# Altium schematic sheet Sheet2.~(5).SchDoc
size B; SheetNumber: 1; SheetTotal: 1
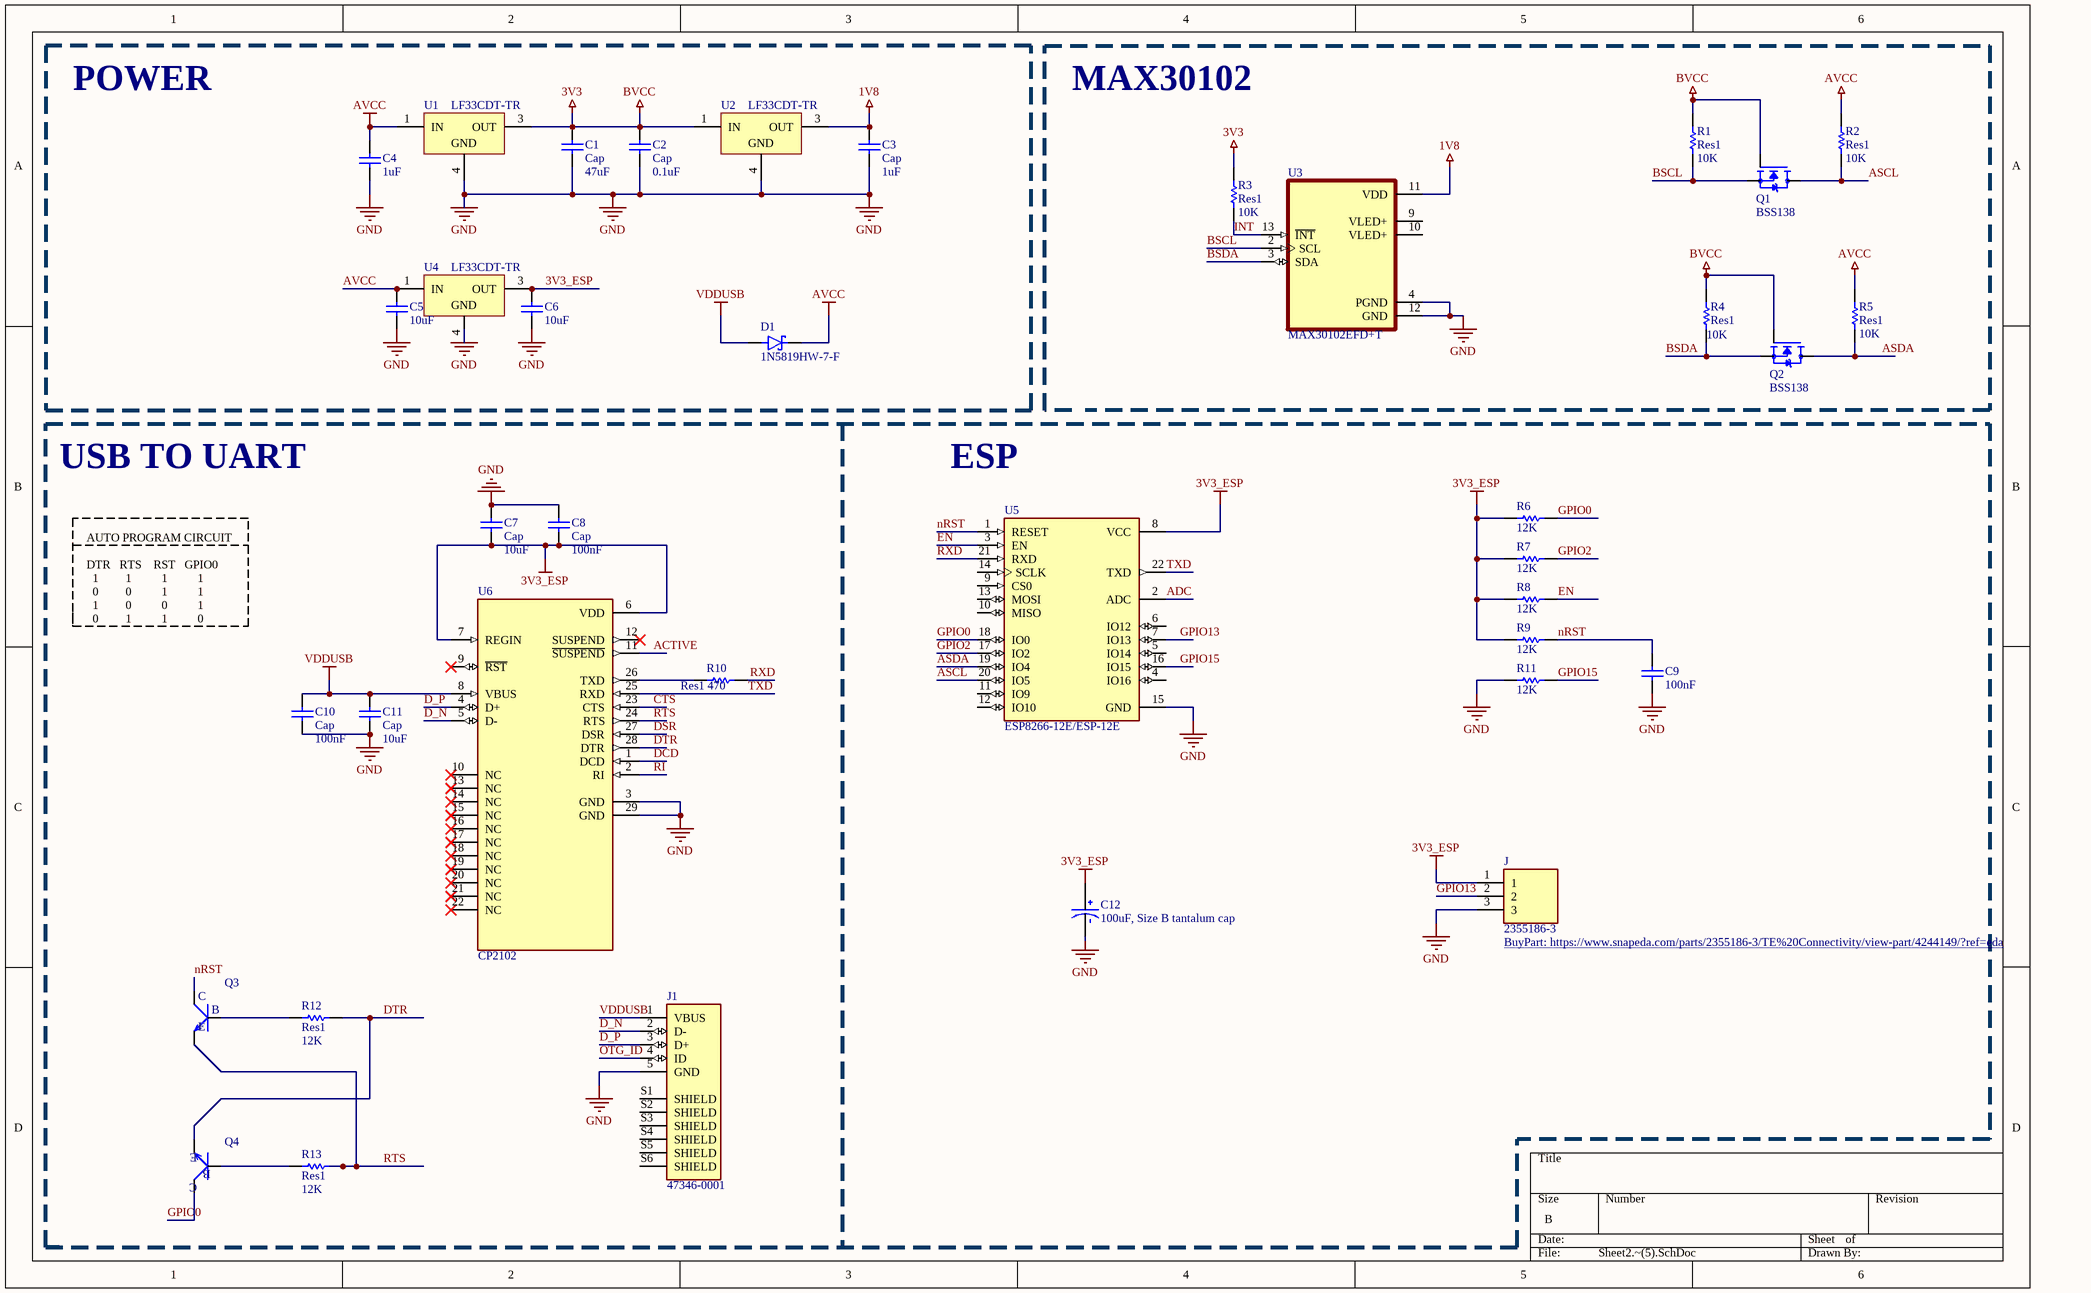
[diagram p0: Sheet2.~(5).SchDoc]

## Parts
C1  Cap  value 47uF  [RAD-0.3]
C2  Cap  value 0.1uF  [RAD-0.3]
C3  Cap  value 1uF  [RAD-0.3]
C4  1uF  [CAP805]
C5  10uF  [CAP805]
C6  10uF  [CAP805]
C7  Cap  value 10uF  [RAD-0.3]
C8  Cap  value 100nF  [RAD-0.3]
C9  100nF  [CAP805]
C10  Cap  value 100nF  [RAD-0.3]
C11  Cap  value 10uF  [RAD-0.3]
C12  100uF, Size B tantalum cap  [CAPMC6032X260]
D1  1N5819HW-7-F  [SOD3715X145N]
J  2355186-3  [TE_2355186-3]
J1  47346-0001  [MOLEX_47346-0001]
Q1  BSS138  [SOT95P240X111-3N]
Q2  BSS138  [SOT95P240X111-3N]
Q3  SMD-TRANSISTORS-NPN-25V-500MW(SOT-23)  [SOT-23]  (value not drawn)
Q4  SMD-TRANSISTORS-NPN-25V-500MW(SOT-23)  [SOT-23]  (value not drawn)
R1  Res1  value 10K  [AXIAL-0.3]
R2  Res1  value 10K  [AXIAL-0.3]
R3  Res1  value 10K  [AXIAL-0.3]
R4  Res1  value 10K  [AXIAL-0.3]
R5  Res1  value 10K  [AXIAL-0.3]
R6  12K  [RES0805]
R7  12K  [RES0805]
R8  12K  [RES0805]
R9  12K  [RES0805]
R10  Res1  value 470  [AXIAL-0.3]
R11  12K  [RES0805]
R12  Res1  value 12K  [AXIAL-0.3]
R13  Res1  value 12K  [AXIAL-0.3]
U1  LF33CDT-TR  [TO-252_N]
U2  LF33CDT-TR  [TO-252_N]
U3  MAX30102EFD+T  [XDCR_MAX30101EFD+]
U4  LF33CDT-TR  [TO-252_N]
U5  ESP8266-12E/ESP-12E  [XCVR_ESP8266-12E/ESP-12E]
U6  CP2102  [QFN50P500X500X100-29N]

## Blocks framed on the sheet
POWER: C1-C6 D1 U1 U2 U4

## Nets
1V8: C3.2 U2.3(OUT) U3.11(VDD)
3V3: C1.2 C2.2 Q1.1(G) Q2.1(G) R1.2 R3.2 R4.2 U1.3(OUT) U2.1(IN)  [also labelled BVCC]
3V3_ESP: C6.2 C7.2 C8.2 C12.POS J.1 R6.1 R7.1 R8.1 R9.1 U4.3(OUT) U5.8(VCC) U6.6(VDD) U6.7(REGIN)
AVCC: C4.2 C5.2 D1.C(K) R2.2 R5.2 U1.1(IN) U4.1(IN)
GND: C1.1 C2.1 C3.1 C4.1 C5.1 C6.1 C7.1 C8.1 C9.1 C10.1 C11.1 C12.NEG J.3 J1.5(GND) R11.1 U1.4(GND) U2.4(GND) U3.4(PGND) U3.12(GND) U4.4(GND) U5.15(GND) U6.3(GND) U6.29(GND)
VDDUSB: C10.2 C11.2 D1.A J1.1(VBUS) U6.8(VBUS)
ACTIVE: U6.11(~{SUSPEND})
ADC: U5.2(ADC)
ASCL: Q1.3(D) R2.1 U5.20(IO5)
ASDA: Q2.3(D) R5.1 U5.19(IO4)
BSCL: Q1.2(S) R1.1 U3.2(SCL)
BSDA: Q2.2(S) R4.1 U3.3(SDA)
CTS: U6.23(CTS)
D_N: J1.2(D-) U6.5(D-)
D_P: J1.3(D+) U6.4(D+)
DCD: U6.1(DCD)
DSR: U6.27(DSR)
DTR: Q4.2(E) R12.2 U6.28(DTR)
EN: R8.2 U5.3(EN)
GPIO0: Q4.3(C) R6.2 U5.18(IO0)
GPIO2: R7.2 U5.17(IO2)
GPIO13: J.2 U5.7(IO13)
GPIO15: R11.2 U5.16(IO15)
INT: R3.1 U3.13(~{INT})
nRST: C9.2 Q3.3(C) R9.2 U5.1(RESET)
OTG_ID: J1.4(ID)
RI: U6.2(RI)
RTS: Q3.2(E) R13.2 U6.24(RTS)
RXD: R10.2 U5.21(RXD)
TXD: U5.22(TXD) U6.25(RXD)
NetQ3_1: Q3.1(B) R12.1
NetQ4_1: Q4.1(B) R13.1
NetR10_1: R10.1 U6.26(TXD)

Not connected (* = marked no-connect by the designer): J1 S1(SHIELD) S2(SHIELD) S3(SHIELD) S4(SHIELD) S5(SHIELD) S6(SHIELD); U3 9(VLED+) 10(VLED+); U5 4(IO16) 5(IO14) 6(IO12) 9(CS0) 10(MISO) 11(IO9) 12(IO10) 13(MOSI) 14(SCLK); U6 9(~{RST})* 10(NC)* 12(SUSPEND)* 13(NC)* 14(NC)* 15(NC)* 16(NC)* 17(NC)* 18(NC)* 19(NC)* 20(NC)* 21(NC)* 22(NC)*

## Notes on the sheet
- MAX30102
- USB TO UART
- ESP
- AUTO PROGRAM CIRCUIT
  DTR   RTS    RST   GPIO0
  1         1          1          1
  0         0          1          1
  1         0          0          1
  0         1          1          0

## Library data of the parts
C1-C3 C7 C8 C10 C11 = Cap: Capacitor
C4 = CAP SMD PACKAGE: TOTAL CAPACITOR SMD PACK; Designer: Abbas Basereh; Desc.: CAP SMD TOTAL PACKAGES; VALUE: 100nF
C5 C6 C9 = CAP SMD PACKAGE: TOTAL CAPACITOR SMD PACK; Designer: Abbas Basereh; Desc.: CAP SMD TOTAL PACKAGES
C12 = TAJC107K016RNJ: 100µF Molded Tantalum Capacitors 16V 2312 _6032 Metric_ 1Ohm; MF: AVX Interconnect / Elco
D1 = 1N5819HW-7-F: Diode Schottky 40 V 1A Surface Mount SOD-123; MF: Diodes Inc.
J = 2355186-3: Pin 3P,2MM,BRK HDR,SRVT,2.8,0.76AU,BOX 3 POS; MF: TE Connectivity
J1 = 47346-0001: USB - micro B USB 2.0 Receptacle Connector 5 Position Surface Mount, Right Angle; MF: Molex
Q1 Q2 = BSS138: N-Channel 50 V 220mA (Ta) 350mW (Ta) Surface Mount SOT-23-3; MF: onsemi
Q3 Q4 = SMD-TRANSISTORS-NPN-25V-500MW(SOT-23): Bipolar (BJT) Transistor NPN 25 V 500 mA 150MHz 300 mW Surface Mount SOT-23; MF: UMW; MP: S8050
R1-R5 R10 R12 R13 = Res1: Resistor
R6-R9 R11 = RES SMD PACKAGE: TOTAL SMD RESISTOR PACK; Designer: Abbas Basereh; Desc.: RES SMD PAKAGES
U1 U2 U4 = LF33CDT-TR: 500mA, Very Low Drop (0.45V) Voltage Regulator, 3.3V, 3-Pin DPAK, Tape and Reel
U3 = MAX30102EFD+T: Pulse Oximeter and Heart Rate Sensor Digital Output; MF: Maxim Integrated Products
U5 = ESP8266-12E/ESP-12E: This WiFi module has a 32-bit MCU micro and clock speeds supporting 80 MHz or 160 MHz. Supports the RTOS and integrated Wi-Fi MAC/BB/RF/PA/LNA, and has an on-board antenna.; MF: AI-Thinker
U6 = CP2102: CP2102N USB 2.0 to UART (RS232) Bridge Interface Evaluation Board; MF: Silicon Labs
